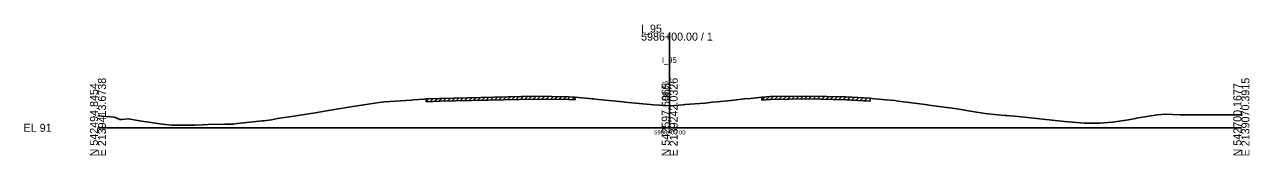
# Model space of a CAD drawing. Extents: x -12534 to 3403, y -1332 to 21983.
# Drawn here: x -25.7 to 402.8, y 16490.3 to 16536.1 of the extents above; entities that cross this region are included whole.
import ezdxf

# ---------------------------------------------------------------- set-up
doc = ezdxf.new("R2010")
doc.units = 0
for name, color, linetype in [('RD_GPK_XS_Cell', 7, 'Continuous'), ('RD_XS_ExGround', 7, 'Continuous'), ('RD_XS_ExPaveRet', 7, 'Continuous'), ('RD_XS_TX_Baseline', 7, 'Continuous'), ('RD_XS_TX_Elev_EX', 7, 'Continuous'), ('RD_XS_TX_Station', 7, 'Continuous')]:
    doc.layers.add(name, color=color, linetype=linetype)

msp = doc.modelspace()

# ---------------------------------------------------------------- linework, layer by layer
at = {"layer": 'RD_GPK_XS_Cell'}
for p, q in [((200, 16500), (200, 16533.29)), ((0, 16500), (200, 16500)), ((200, 16500), (400, 16500))]:
    msp.add_line(p, q, dxfattribs=at)
at = {"layer": 'RD_XS_ExGround'}
msp.add_lwpolyline([(0, 16504.24), (5.74, 16503.71), (7.69, 16502.9), (8.39, 16502.93), (10.56, 16503.08), (14.64, 16502.43), (15.31, 16502.34), (22.59, 16501.22), (25.78, 16500.95), (29.3, 16500.88), (33.09, 16500.95), (33.93, 16500.96), (36.53, 16501.03), (38.41, 16501.13), (44.33, 16501.23), (47.34, 16501.32), (48.76, 16501.5), (57.45, 16502.41), (58.18, 16502.47), (60.68, 16502.84), (62.85, 16503.2), (68.48, 16504.07), (76.04, 16505.29), (78.66, 16505.72), (79.96, 16505.94), (89.13, 16507.48), (93.78, 16508.19), (98.4, 16508.83), (99.43, 16508.96), (100.27, 16509.1), (107.76, 16509.59), (109.68, 16509.72), (110.32, 16509.75), (114.11, 16510.04), (114.77, 16510.13), (119.59, 16510.28), (152.93, 16511.04), (164.6, 16510.85), (166.98, 16510.75), (172.92, 16510.15), (173.37, 16510.09), (175.08, 16509.93), (183.62, 16509.06), (184.34, 16509), (186.75, 16508.76), (194.52, 16508.04), (196.61, 16507.9), (200.09, 16507.65), (204.71, 16508.07), (205.32, 16508.12), (212.38, 16508.66), (214.87, 16508.91), (216.6, 16509.05), (221.45, 16509.57), (226.13, 16510.1), (228.23, 16510.28), (231.36, 16510.58), (232.19, 16510.67), (235.2, 16510.9), (248.38, 16511.1), (261.66, 16510.82), (270.18, 16510.34), (270.67, 16510.25), (275.65, 16509.77), (278.78, 16509.49), (279.82, 16509.35), (282.81, 16509.02), (284.66, 16508.76), (289.34, 16508.09), (291.47, 16507.78), (299.77, 16506.74), (307.31, 16505.47), (310.42, 16505.01), (314.72, 16504.59), (317.39, 16504.3), (317.93, 16504.27), (321.91, 16503.91), (338.15, 16502.21), (345.16, 16501.59), (346.3, 16501.62), (350.33, 16501.59), (354.87, 16502.02), (360.53, 16502.8), (362.92, 16503.25), (363.28, 16503.33), (370.54, 16504.51), (373.5, 16504.79), (378.44, 16504.59), (384.16, 16504.55), (387.78, 16504.53), (393.17, 16504.49), (400, 16504.52)], dxfattribs=at)
at = {"layer": 'RD_XS_ExPaveRet'}
for p, q in [((114.77, 16509.13), (115.8, 16510.16)), ((114.77, 16509.13), (114.77, 16510.13)), ((114.77, 16509.13), (119.59, 16509.28)), ((116.27, 16509.18), (117.3, 16510.21)), ((117.77, 16509.22), (118.8, 16510.25)), ((119.27, 16509.27), (120.29, 16510.29)), ((119.59, 16509.28), (152.93, 16510.04)), ((120.77, 16509.31), (121.79, 16510.33)), ((122.27, 16509.34), (123.29, 16510.36)), ((123.77, 16509.37), (124.79, 16510.4)), ((125.27, 16509.41), (126.29, 16510.43)), ((126.77, 16509.44), (127.79, 16510.46)), ((128.27, 16509.48), (129.29, 16510.5)), ((129.77, 16509.51), (130.79, 16510.53)), ((131.27, 16509.54), (132.29, 16510.57)), ((132.77, 16509.58), (133.79, 16510.6)), ((134.27, 16509.61), (135.29, 16510.64)), ((135.77, 16509.65), (136.79, 16510.67)), ((137.27, 16509.68), (138.29, 16510.7)), ((138.77, 16509.71), (139.79, 16510.74)), ((140.27, 16509.75), (141.29, 16510.77)), ((141.77, 16509.78), (142.79, 16510.81)), ((143.27, 16509.82), (144.29, 16510.84)), ((144.77, 16509.85), (145.79, 16510.87)), ((146.27, 16509.88), (147.29, 16510.91)), ((147.77, 16509.92), (148.79, 16510.94)), ((149.27, 16509.95), (150.29, 16510.98)), ((150.77, 16509.99), (151.79, 16511.01)), ((152.27, 16510.02), (153.28, 16511.03)), ((152.93, 16510.04), (164.6, 16509.85)), ((153.77, 16510.02), (154.75, 16511.01)), ((155.27, 16510), (156.25, 16510.98)), ((156.77, 16509.97), (157.75, 16510.96)), ((158.27, 16509.95), (159.25, 16510.94)), ((159.77, 16509.93), (160.75, 16510.91)), ((161.27, 16509.9), (162.25, 16510.89)), ((162.77, 16509.88), (163.75, 16510.86)), ((164.27, 16509.86), (165.23, 16510.82)), ((164.6, 16509.85), (166.98, 16509.75)), ((165.77, 16509.8), (166.73, 16510.76)), ((166.98, 16510.75), (166.98, 16509.75)), ((232.19, 16509.67), (233.27, 16510.75)), ((232.19, 16509.67), (232.19, 16510.67)), ((232.19, 16509.67), (235.2, 16509.9)), ((233.69, 16509.79), (234.77, 16510.87)), ((235.19, 16509.9), (236.21, 16510.91)), ((235.2, 16509.9), (248.38, 16510.1)), ((236.69, 16509.92), (237.7, 16510.94)), ((238.19, 16509.94), (239.2, 16510.96)), ((239.69, 16509.97), (240.7, 16510.98)), ((241.19, 16509.99), (242.2, 16511)), ((242.69, 16510.01), (243.7, 16511.03)), ((244.19, 16510.03), (245.2, 16511.05)), ((245.69, 16510.06), (246.7, 16511.07)), ((247.19, 16510.08), (248.2, 16511.09)), ((248.38, 16510.1), (261.66, 16509.82)), ((248.69, 16510.09), (249.67, 16511.07)), ((250.19, 16510.06), (251.17, 16511.04)), ((251.69, 16510.03), (252.67, 16511.01)), ((253.19, 16510), (254.17, 16510.98)), ((254.69, 16509.97), (255.67, 16510.95)), ((256.19, 16509.94), (257.17, 16510.92)), ((257.69, 16509.91), (258.67, 16510.88)), ((259.19, 16509.87), (260.17, 16510.85)), ((260.69, 16509.84), (261.67, 16510.82)), ((261.66, 16509.82), (270.18, 16509.34)), ((262.19, 16509.79), (263.14, 16510.74)), ((263.69, 16509.71), (264.64, 16510.66)), ((265.19, 16509.62), (266.14, 16510.57)), ((266.69, 16509.54), (267.64, 16510.49)), ((268.19, 16509.45), (269.14, 16510.4)), ((270.18, 16510.34), (270.18, 16509.34))]:
    msp.add_line(p, q, dxfattribs=at)

# ---------------------------------------------------------------- texts
at = {"layer": 'RD_GPK_XS_Cell'}
for s, p in [('5986+00.00 / 1', (190, 16530.49)), ('I_95', (190, 16533.29)), ('EL 91', (-26, 16498.6))]:
    msp.add_text(s, height=2.8, dxfattribs=at).set_placement(p)
for s, p in [('E 2139413.6738', (2.8, 16490)), ('E 2139242.0326', (202.8, 16490)), ('E 2139070.3915', (402.8, 16490)), ('N 542494.8454', (0, 16490)), ('N 542597.5065', (200, 16490)), ('N 542700.1677', (400, 16490))]:
    msp.add_text(s, height=2.8, rotation=90, dxfattribs=at).set_placement(p)
at = {"layer": 'RD_XS_TX_Baseline'}
msp.add_text('I_95', height=2, dxfattribs=at).set_placement((197.28, 16522.66))
at = {"layer": 'RD_XS_TX_Elev_EX'}
msp.add_text('98.66', height=2, rotation=90, dxfattribs=at).set_placement((199.5, 16509.66))
at = {"layer": 'RD_XS_TX_Station'}
msp.add_text('5986+00.00', height=1.5, dxfattribs=at).set_placement((194.56, 16497.66))

doc.saveas('drawing.dxf')
